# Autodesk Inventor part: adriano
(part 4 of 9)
sketch "スケッチ127"
  geometry: L1 (0.25, 9.936)-(0.25, 8.736) reference; L2 (0.25, 8.736)-(-0.75, 8.736) reference; L3 (-0.75, 8.736)-(-0.75, 9.936) reference; L4 (-0.75, 9.936)-(0.25, 9.936) reference; L5 (-12.75, 9.936)-(-12.75, 8.736) reference; L6 (-12.75, 8.736)-(-13.75, 8.736) reference; L7 (-13.75, 8.736)-(-13.75, 9.936) reference; L8 (-13.75, 9.936)-(-12.75, 9.936) reference; L9 (-12.75, 4.836)-(-12.75, 3.636) reference; L10 (-12.75, 3.636)-(-13.75, 3.636) reference; L11 (-13.75, 3.636)-(-13.75, 4.836) reference; L12 (-13.75, 4.836)-(-12.75, 4.836) reference; L13 (-12.75, 6.536)-(-12.75, 5.336) reference; L14 (-12.75, 5.336)-(-13.75, 5.336) reference; L15 (-13.75, 5.336)-(-13.75, 6.536) reference; L16 (-13.75, 6.536)-(-12.75, 6.536) reference; L17 (-12.75, 8.236)-(-12.75, 7.036) reference; L18 (-12.75, 7.036)-(-13.75, 7.036) reference; L19 (-13.75, 7.036)-(-13.75, 8.236) reference; L20 (-13.75, 8.236)-(-12.75, 8.236) reference; L21 (-1.25, 4.836)-(-1.25, 3.636) reference; L22 (-1.25, 3.636)-(-2.25, 3.636) reference; L23 (-2.25, 3.636)-(-2.25, 4.836) reference; L24 (-2.25, 4.836)-(-1.25, 4.836) reference; L25 (-1.25, 6.536)-(-1.25, 5.336) reference; L26 (-1.25, 5.336)-(-2.25, 5.336) reference; L27 (-2.25, 5.336)-(-2.25, 6.536) reference; L28 (-2.25, 6.536)-(-1.25, 6.536) reference; L29 (-1.25, 8.236)-(-1.25, 7.036) reference; L30 (-1.25, 7.036)-(-2.25, 7.036) reference; L31 (-2.25, 7.036)-(-2.25, 8.236) reference; L32 (-2.25, 8.236)-(-1.25, 8.236) reference; L33 (-13.75, 10.436)-(-13.75, 11.436) reference; L34 (-12.75, 10.436)-(-13.75, 10.436) reference; L35 (-0.75, 10.436)-(-0.75, 11.436) reference; L36 (0.25, 10.436)-(-0.75, 10.436) reference; L37 (-1.25, 10.436)-(-2.25, 10.436) reference; L38 (-1.25, 11.436)-(-1.25, 10.436) reference; L39 (-14.25, 10.436)-(-15.25, 10.436) reference; L40 (-14.25, 11.436)-(-14.25, 10.436) reference; L41 (0.25, 8.236)-(0.25, 7.036) reference; L42 (0.25, 7.036)-(-0.75, 7.036) reference; L43 (-0.75, 7.036)-(-0.75, 8.236) reference; L44 (-0.75, 8.236)-(0.25, 8.236) reference; L45 (0.25, 6.536)-(0.25, 5.336) reference; L46 (0.25, 5.336)-(-0.75, 5.336) reference; L47 (-0.75, 5.336)-(-0.75, 6.536) reference; L48 (-0.75, 6.536)-(0.25, 6.536) reference; L49 (0.25, 4.836)-(0.25, 3.636) reference; L50 (0.25, 3.636)-(-0.75, 3.636) reference; L51 (-0.75, 3.636)-(-0.75, 4.836) reference; L52 (-0.75, 4.836)-(0.25, 4.836) reference; L53 (-14.25, 8.236)-(-14.25, 7.036) reference; L54 (-14.25, 7.036)-(-15.25, 7.036) reference; L55 (-15.25, 7.036)-(-15.25, 8.236) reference; L56 (-15.25, 8.236)-(-14.25, 8.236) reference; L57 (-14.25, 6.536)-(-14.25, 5.336) reference; L58 (-14.25, 5.336)-(-15.25, 5.336) reference; L59 (-15.25, 5.336)-(-15.25, 6.536) reference; L60 (-15.25, 6.536)-(-14.25, 6.536) reference; L61 (-14.25, 4.836)-(-14.25, 3.636) reference; L62 (-14.25, 3.636)-(-15.25, 3.636) reference; L63 (-15.25, 3.636)-(-15.25, 4.836) reference; L64 (-15.25, 4.836)-(-14.25, 4.836) reference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; A1 r 1 centre (-13.75, 10.436) between (-12.75, 10.436) and (-13.75, 11.436) reference; A2 r 1 centre (-0.75, 10.436) between (0.25, 10.436) and (-0.75, 11.436) reference; A3 r 1 centre (-1.25, 10.436) between (-1.25, 11.436) and (-2.25, 10.436) reference; A4 r 1 centre (-14.25, 10.436) between (-14.25, 11.436) and (-15.25, 10.436) reference; A5 r 2 centre (-1, 10.436) between (1, 10.436) and (-3, 10.436); A6 r 2 centre (-14, 10.436) between (-12, 10.436) and (-16, 10.436); 2 further points
  constraints: 12 end point, 4 point on circle, 3 parallel, 3 perpendicular, 3 tangent, 2 centre point, 2 point on line
  dimensions: "d1680" = 3 distance between parallel lines of L73 L78; "d1681" = 4 distance of L77.end L78.end; "d1682" = 2 distance between parallel lines of L74 L79; "d1683" = 3 distance between parallel lines of L75 L81; "d1684" = 4 distance of L80.end L81.end; "d1685" = 2 distance between parallel lines of L83 L80
extrude "押し出し118" cut sketch "スケッチ127" distance "d1686" = 0.5; taper "d1687" = 0 deg
sketch "スケッチ129"
  geometry: L1 (86.588, 32.686)-(82.588, 32.686) reference; L2 (86.588, 32.686)-(86.588, 40.686) reference; L3 (86.588, 40.686)-(55.588, 40.686) reference; L4 (55.588, 40.686)-(55.588, 32.686) reference; L5 (59.588, 39.186)-(82.588, 39.186) reference; L6 (59.588, 39.186)-(59.588, 40.186) reference; L7 (59.588, 40.186)-(82.588, 40.186) reference; L8 (82.588, 40.186)-(82.588, 39.186) reference; L9 (56.588, 40.686)-(85.588, 40.686); L10 (85.588, 40.686)-(85.588, 32.686); L11 (85.588, 32.686)-(56.588, 32.686); L12 (56.588, 32.686)-(56.588, 40.686); 1 further point
  constraints: 8 end point, 2 parallel, 2 point on line, 1 horizontal, 1 perpendicular
  dimensions: "d1690" = 1 distance between parallel lines of L12 L4; "d1691" = 1 distance between parallel lines of L2 L10
extrude "押し出し119" join sketch "スケッチ129" distance "d1692" = 1; taper "d1693" = 0 deg
sketch "スケッチ130"
  geometry: L1 (29.588, -11.314)-(29.588, 10.686) reference; L2 (60.588, -11.314)-(29.588, -11.314) reference; L3 (81.588, -24.314)-(60.588, -24.314) reference; L4 (81.588, 23.686)-(81.588, -24.314) reference; L5 (60.588, 23.686)-(71.088, 23.686) reference; L6 (60.588, 10.686)-(60.588, 23.686) reference; L7 (29.588, 10.686)-(60.588, 10.686) reference; L8 (31.588, 8.686)-(31.588, -9.314); L9 (31.588, -9.314)-(62.588, -9.314); L10 (62.588, -9.314)-(62.588, -22.314); L11 (62.588, -22.314)-(79.588, -22.314); L12 (79.588, -22.314)-(79.588, 21.686); L13 (79.588, 21.686)-(62.588, 21.686); L14 (62.588, 21.686)-(62.588, 8.686); L15 (62.588, 8.686)-(31.588, 8.686); 1 further point
  constraints: 16 end point, 4 parallel, 4 perpendicular
  dimensions: "d1694" = 2 distance between parallel lines of L15 L7; "d1695" = 2 distance between parallel lines of L1 L8; "d1696" = 2 distance between parallel lines of L2 L9; "d1697" = 2 distance between parallel lines of L4 L12; "d1698" = 2 distance between parallel lines of L14 L6; "d1699" = 2 distance between parallel lines of L13 L5; "d1700" = 0 distance between parallel lines of L10 L14; "d1702" = 2 distance between parallel lines of L3 L11
extrude "押し出し120" cut sketch "スケッチ130" distance "d1703" = 12; taper "d1704" = 0 deg
sketch "スケッチ131"
  geometry: L1 (-30.683, 26.8)-(-30.683, 29.2) reference; L2 (-30.683, 29.2)-(-29.883, 29.2) reference; L3 (-29.883, 26.8)-(-30.683, 26.8) reference; L4 (-31.483, 29.2)-(-32.283, 29.2); L5 (-32.283, 29.2)-(-32.283, 26.8); L6 (-32.283, 26.8)-(-31.483, 26.8); L7 (-31.483, 26.8)-(-31.483, 29.2); L8 (-33.083, 29.2)-(-33.883, 29.2); L9 (-33.883, 29.2)-(-33.883, 26.8); L10 (-33.883, 26.8)-(-33.083, 26.8); L11 (-33.083, 26.8)-(-33.083, 29.2); L12 (-61.5, 29.2)-(-60.7, 29.2); L13 (-60.7, 29.2)-(-60.7, 26.749); L14 (-60.7, 26.749)-(-61.5, 26.749); L15 (-61.5, 26.749)-(-61.5, 29.2); L16 (-59.9, 29.2)-(-59.1, 29.2); L17 (-59.1, 29.2)-(-59.1, 26.749); L18 (-59.1, 26.749)-(-59.9, 26.749); L19 (-59.9, 26.749)-(-59.9, 29.2); L20 (-62.3, 29.2)-(-62.3, 26.749) reference; L21 (-62.3, 26.749)-(-63.1, 26.749) reference; 1 further point
  constraints: 32 end point, 8 parallel, 4 horizontal, 4 perpendicular
  dimensions: "d1705" = 0.8 distance of L4.start L4.end; "d1707" = 0.8 distance between parallel lines of L1 L7; "d1708" = 0.8 distance between parallel lines of L5 L11; "d1709" = 0 distance between parallel lines of L3 L6; "d1710" = 0 distance between parallel lines of L6 L10; "d1711" = 0 distance between parallel lines of L4 L8; "d1712" = 0 distance between parallel lines of L2 L4; "d1713" = 0.8 distance of L8.start L8.end; "d1714" = 0.8 distance of L12.start L12.end; "d1715" = 0.8 distance of L16.start L16.end; "d1716" = 0.8 distance between parallel lines of L19 L13; "d1717" = 0.8 distance between parallel lines of L15 L20; "d1718" = 0 distance between parallel lines of L14 L21; "d1719" = 0 distance between parallel lines of L18 L14
extrude "押し出し121" cut sketch "スケッチ131" distance "d1720" = 2; taper "d1721" = 0 deg
sketch "スケッチ132"
  geometry: L1 (-0.5, -19.064)-(30.5, -19.064) reference; L2 (4, -8.3)-(5, -8.3); L3 (5, -8.3)-(5, -9.5); L4 (5, -9.5)-(4, -9.5); L5 (4, -9.5)-(4, -8.3); L6 (5.5, -8.3)-(6.5, -8.3); L7 (6.5, -8.3)-(6.5, -9.5); L8 (6.5, -9.5)-(5.5, -9.5); L9 (5.5, -9.5)-(5.5, -8.3); L10 (10.5, -8.3)-(11.5, -8.3); L11 (11.5, -8.3)-(11.5, -9.5); L12 (11.5, -9.5)-(10.5, -9.5); L13 (10.5, -9.5)-(10.5, -8.3); L14 (12, -8.3)-(13, -8.3); L15 (13, -8.3)-(13, -9.5); L16 (13, -9.5)-(12, -9.5); L17 (12, -9.5)-(12, -8.3); L18 (17, -8.3)-(18, -8.3); L19 (18, -8.3)-(18, -9.5); L20 (18, -9.5)-(17, -9.5); L21 (17, -9.5)-(17, -8.3); L22 (18.5, -8.3)-(19.5, -8.3); L23 (19.5, -8.3)-(19.5, -9.5); L24 (19.5, -9.5)-(18.5, -9.5); L25 (18.5, -9.5)-(18.5, -8.3); L26 (23.5, -8.3)-(24.5, -8.3); L27 (24.5, -8.3)-(24.5, -9.5); L28 (24.5, -9.5)-(23.5, -9.5); L29 (23.5, -9.5)-(23.5, -8.3); L30 (25, -8.3)-(26, -8.3); L31 (26, -8.3)-(26, -9.5); L32 (26, -9.5)-(25, -9.5); L33 (25, -9.5)-(25, -8.3); L34 (10.5, -7.8)-(10.5, -6.6); L35 (10.5, -6.6)-(11.5, -6.6); L36 (11.5, -7.8)-(10.5, -7.8); L37 (11.5, -6.6)-(11.5, -7.8); L38 (12, -7.8)-(12, -6.6); L39 (13, -6.6)-(13, -7.8); L40 (13, -7.8)-(12, -7.8); L41 (12, -6.6)-(13, -6.6); L42 (17, -7.8)-(17, -6.6); L43 (17, -6.6)-(18, -6.6); L44 (18, -7.8)-(17, -7.8); L45 (18, -6.6)-(18, -7.8); L46 (18.5, -7.8)-(18.5, -6.6); L47 (19.5, -6.6)-(19.5, -7.8); L48 (18.5, -6.6)-(19.5, -6.6); L49 (19.5, -7.8)-(18.5, -7.8); L50 (23.5, -7.8)-(23.5, -6.6); L51 (23.5, -6.6)-(24.5, -6.6); L52 (24.5, -6.6)-(24.5, -7.8); L53 (25, -7.8)-(25, -6.6); L54 (25, -6.6)-(26, -6.6); L55 (26, -6.6)-(26, -7.8); L56 (26, -7.8)-(25, -7.8); L57 (24.5, -7.8)-(23.5, -7.8); L58 (6.5, -6.6)-(6.5, -7.8); L59 (5.5, -6.6)-(6.5, -6.6); L60 (6.5, -7.8)-(5.5, -7.8); L61 (5.5, -7.8)-(5.5, -6.6); L62 (5, -6.6)-(5, -7.8); L63 (4, -6.6)-(5, -6.6); L64 (5, -7.8)-(4, -7.8)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; A1 r 1 centre (5, -23.564) between (5, -22.564) and (4, -23.564); A2 r 1 centre (5.5, -23.564) between (6.5, -23.564) and (5.5, -22.564); A3 r 1 centre (11.5, -23.564) between (11.5, -22.564) and (10.5, -23.564); A4 r 1 centre (12, -23.564) between (13, -23.564) and (12, -22.564); A5 r 1 centre (18, -23.564) between (18, -22.564) and (17, -23.564); A6 r 1 centre (18.5, -23.564) between (19.5, -23.564) and (18.5, -22.564); A7 r 1 centre (24.5, -23.564) between (24.5, -22.564) and (23.5, -23.564); A8 r 1 centre (25, -23.564) between (26, -23.564) and (25, -22.564); 2 further points
  constraints: 544 end point, 131 parallel, 75 perpendicular, 64 horizontal, 16 point on circle, 8 centre point, 2 collinear
  dimensions: "d1722" = 1 distance of L63.start L62.start; "d1724" = 0.5 distance between parallel lines of L61 L62; "d1725" = 1 distance of L59.start L58.start; "d1726" = 4 distance between parallel lines of L34 L58; "d1727" = 1 distance of L34.end L35.end; "d1728" = 0.5 distance between parallel lines of L38 L37; "d1729" = 1 distance of L38.end L39.start; "d1730" = 1 distance of L42.end L43.end; "d1731" = 0.5 distance between parallel lines of L46 L45; "d1732" = 1 distance of L46.end L47.start; "d1733" = 1 distance of L50.end L51.end; "d1734" = 0.5 distance between parallel lines of L53 L52; "d1735" = 1 distance of L53.end L54.end; "d1736" = 4 distance between parallel lines of L50 L47; "d1737" = 4 distance between parallel lines of L42 L39; "d1738" = 0 distance between parallel lines of L55 L31; "d1739" = 0 distance between parallel lines of L31 L107; "d1740" = 0 distance between parallel lines of L107 L98; "d1741" = 0 distance between parallel lines of L52 L27; "d1742" = 0 distance between parallel lines of L27 L111; "d1743" = 0 distance between parallel lines of L111 L102; "d1744" = 0 distance between parallel lines of L47 L23; "d1745" = 0 distance between parallel lines of L90 L23; "d1746" = 0 distance between parallel lines of L87 L90; "d1747" = 0 distance between parallel lines of L45 L19; "d1748" = 0 distance between parallel lines of L19 L94; "d1749" = 0 distance between parallel lines of L94 L83; "d1750" = 0 distance between parallel lines of L39 L15; "d1751" = 0 distance between parallel lines of L15 L80; "d1752" = 0 distance between parallel lines of L80 L71; "d1753" = 0 distance between parallel lines of L11 L37; "d1754" = 0 distance between parallel lines of L76 L11; "d1755" = 0 distance between parallel lines of L76 L67; "d1756" = 0 distance between parallel lines of L13 L34; "d1757" = 0 distance between parallel lines of L73 L13; "d1758" = 0 distance between parallel lines of L69 L73; "d1759" = 0 distance between parallel lines of L21 L42; "d1760" = 0 distance between parallel lines of L96 L21; "d1761" = 0 distance between parallel lines of L85 L96; "d1762" = 0 distance between parallel lines of L25 L46; "d1763" = 0 distance between parallel lines of L93 L25; "d1764" = 0 distance between parallel lines of L89 L93; "d1765" = 0 distance between parallel lines of L29 L50; "d1766" = 0 distance between parallel lines of L112 L29; "d1767" = 0 distance between parallel lines of L105 L112; "d1768" = 0 distance between parallel lines of L33 L53; "d1769" = 0 distance between parallel lines of L109 L33; "d1770" = 0 distance between parallel lines of L101 L109; "d1771" = 0 distance between parallel lines of L17 L38; "d1772" = 0 distance between parallel lines of L77 L17; "d1773" = 0 distance between parallel lines of L78 L77; "d1774" = 0 distance between parallel lines of L9 L61; "d1775" = 0 distance between parallel lines of L125 L9; "d1776" = 0 distance between parallel lines of L119 L125; "d1777" = 0 distance between parallel lines of L7 L58; "d1778" = 0 distance between parallel lines of L123 L7; "d1779" = 0 distance between parallel lines of L118 L123; "d1780" = 1.2 distance of L64.end L63.start; "d1781" = 0.5 distance between parallel lines of L2 L64; "d1782" = 0.5 distance between parallel lines of L4 L127; "d1783" = 0.5 distance between parallel lines of L121 L129; "d1784" = 1.2 distance of L4.end L2.start; "d1785" = 1.2 distance of L128.start L127.start; "d1786" = 1.2 distance of L114.end L117.end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
extrude "押し出し122" cut sketch "スケッチ132" distance "d1985" = 30; taper "d1986" = 0 deg
sketch "スケッチ133"
  geometry: L1 (5.5, -10)-(6.5, -10) reference; L2 (6.5, -10)-(6.5, -11.2) reference; L3 (6.5, -11.2)-(5.5, -11.2) reference; L4 (5.5, -11.2)-(5.5, -10) reference; L5 (23.5, -10)-(24.5, -10) reference; L6 (24.5, -10)-(24.5, -11.2) reference; L7 (24.5, -11.2)-(23.5, -11.2) reference; L8 (23.5, -11.2)-(23.5, -10) reference; L9 (23.5, -11.7)-(24.5, -11.7) reference; L10 (24.5, -11.7)-(24.5, -12.9) reference; L11 (24.5, -12.9)-(23.5, -12.9) reference; L12 (23.5, -12.9)-(23.5, -11.7) reference; L13 (18.5, -11.2)-(18.5, -10) reference; L14 (18.5, -10)-(19.5, -10) reference; L15 (19.5, -10)-(19.5, -11.2) reference; L16 (19.5, -11.2)-(18.5, -11.2) reference; L17 (17, -12.9)-(17, -11.7) reference; L18 (17, -11.7)-(18, -11.7) reference; L19 (18, -11.7)-(18, -12.9) reference; L20 (18, -12.9)-(17, -12.9) reference; L21 (10.5, -11.2)-(10.5, -10) reference; L22 (10.5, -10)-(11.5, -10) reference; L23 (11.5, -10)-(11.5, -11.2) reference; L24 (11.5, -11.2)-(10.5, -11.2) reference; L25 (10.5, -12.9)-(10.5, -11.7) reference; L26 (10.5, -11.7)-(11.5, -11.7) reference; L27 (11.5, -11.7)-(11.5, -12.9) reference; L28 (11.5, -12.9)-(10.5, -12.9) reference; L29 (6.5, -11.7)-(6.5, -12.9) reference; L30 (6.5, -12.9)-(5.5, -12.9) reference; L31 (5.5, -12.9)-(5.5, -11.7) reference; L32 (5.5, -11.7)-(6.5, -11.7) reference; L33 (5.5, -6.6)-(6.5, -6.6) reference; L34 (6.5, -6.6)-(6.5, -7.8) reference; L35 (6.5, -7.8)-(5.5, -7.8) reference; L36 (5.5, -7.8)-(5.5, -6.6) reference; L37 (23.5, -7.8)-(23.5, -6.6) reference; L38 (23.5, -6.6)-(24.5, -6.6) reference; L39 (24.5, -6.6)-(24.5, -7.8) reference; L40 (24.5, -7.8)-(23.5, -7.8) reference; L41 (17, -7.8)-(17, -6.6) reference; L42 (17, -6.6)-(18, -6.6) reference; L43 (18, -6.6)-(18, -7.8) reference; L44 (18, -7.8)-(17, -7.8) reference; L45 (10.5, -7.8)-(10.5, -6.6) reference; L46 (10.5, -6.6)-(11.5, -6.6) reference; L47 (11.5, -6.6)-(11.5, -7.8) reference; L48 (11.5, -7.8)-(10.5, -7.8) reference; L49 (23.5, -9.5)-(23.5, -8.3) reference; L50 (23.5, -8.3)-(24.5, -8.3) reference; L51 (24.5, -8.3)-(24.5, -9.5) reference; L52 (24.5, -9.5)-(23.5, -9.5) reference; L53 (17, -9.5)-(17, -8.3) reference; L54 (17, -8.3)-(18, -8.3) reference; L55 (18, -8.3)-(18, -9.5) reference; L56 (18, -9.5)-(17, -9.5) reference; L57 (10.5, -9.5)-(10.5, -8.3) reference; L58 (10.5, -8.3)-(11.5, -8.3) reference; L59 (11.5, -8.3)-(11.5, -9.5) reference; L60 (11.5, -9.5)-(10.5, -9.5) reference; L61 (4, -9.5)-(4, -8.3) reference; L62 (4, -8.3)-(5, -8.3) reference; L63 (5, -8.3)-(5, -9.5) reference; L64 (5, -9.5)-(4, -9.5) reference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; A1 r 2 centre (5.25, -23.564) between (7.25, -23.564) and (3.25, -23.564); A2 r 2 centre (11.75, -23.564) between (13.75, -23.564) and (9.75, -23.564); A3 r 2 centre (18.25, -23.564) between (20.25, -23.564) and (16.25, -23.564); A4 r 2 centre (24.75, -23.564) between (26.75, -23.564) and (22.75, -23.564); 2 further points
  constraints: 56 end point, 16 parallel, 8 perpendicular, 8 point on circle, 8 tangent, 4 centre point, 4 horizontal
  dimensions: "d1987" = 4 distance of L132.end L133.end; "d1989" = 4 distance of L136.end L137.end; "d1990" = 4 distance of L140.end L141.end; "d1991" = 4 distance of L144.end L145.end; "d1992" = 3.75 distance between parallel lines of L129 L144; "d1993" = 2.5 distance between parallel lines of L146 L140; "d1994" = 2.5 distance between parallel lines of L136 L142; "d1995" = 2.5 distance between parallel lines of L132 L138; "d1996" = 0 distance between parallel lines of L147 L134; "d1997" = 0 distance between parallel lines of L149 L132; "d1998" = 0 distance between parallel lines of L150 L138; "d1999" = 0 distance between parallel lines of L152 L136; "d2000" = 0 distance between parallel lines of L153 L142; "d2001" = 0 distance between parallel lines of L155 L140; "d2002" = 0 distance between parallel lines of L158 L144; "d2003" = 0 distance between parallel lines of L146 L156; "d2004" = 4.35 distance between parallel lines of L143 L130; "d2005" = 0 distance between parallel lines of L143 L139; "d2006" = 0 distance from line of L139 L135.end; "d2007" = 0 distance between parallel lines of L131 L135; "d2008" = 7.5 distance of L143.end L144.end; "d2009" = 0 distance from line of L159 A4.centre; "d2010" = 0 vertical distance of A4.centre A3.centre; "d2011" = 0 vertical distance of A3.centre A2.centre; "d2012" = 0 vertical distance of A1.centre A2.centre; "d2013" = 3 distance between parallel lines of L160 L157; "d2014" = 0 distance between parallel lines of L157 L154; "d2015" = 0 distance between parallel lines of L151 L154; "d2016" = 0 distance between parallel lines of L151 L148
extrude "押し出し123" cut sketch "スケッチ133" distance "d2017" = 0.5; taper "d2018" = 0 deg
sketch "スケッチ134"
  geometry: L1 (24.5, -10)-(25.5, -10) reference; L2 (25.5, -10)-(25.5, -11.2) reference; L3 (25.5, -11.2)-(24.5, -11.2) reference; L4 (24.5, -11.2)-(24.5, -10) reference; L5 (6.5, -10)-(7.5, -10) reference; L6 (7.5, -10)-(7.5, -11.2) reference; L7 (7.5, -11.2)-(6.5, -11.2) reference; L8 (6.5, -11.2)-(6.5, -10) reference; L9 (6.5, -11.7)-(7.5, -11.7) reference; L10 (7.5, -11.7)-(7.5, -12.9) reference; L11 (7.5, -12.9)-(6.5, -12.9) reference; L12 (6.5, -12.9)-(6.5, -11.7) reference; L13 (12.5, -10)-(12.5, -11.2) reference; L14 (12.5, -11.2)-(11.5, -11.2) reference; L15 (11.5, -11.2)-(11.5, -10) reference; L16 (11.5, -10)-(12.5, -10) reference; L17 (14, -11.7)-(14, -12.9) reference; L18 (14, -12.9)-(13, -12.9) reference; L19 (13, -12.9)-(13, -11.7) reference; L20 (13, -11.7)-(14, -11.7) reference; L21 (20.5, -10)-(20.5, -11.2) reference; L22 (20.5, -11.2)-(19.5, -11.2) reference; L23 (19.5, -11.2)-(19.5, -10) reference; L24 (19.5, -10)-(20.5, -10) reference; L25 (20.5, -11.7)-(20.5, -12.9) reference; L26 (20.5, -12.9)-(19.5, -12.9) reference; L27 (19.5, -12.9)-(19.5, -11.7) reference; L28 (19.5, -11.7)-(20.5, -11.7) reference; L29 (24.5, -12.9)-(24.5, -11.7) reference; L30 (24.5, -11.7)-(25.5, -11.7) reference; L31 (25.5, -11.7)-(25.5, -12.9) reference; L32 (25.5, -12.9)-(24.5, -12.9) reference; L33 (24.5, -6.6)-(25.5, -6.6) reference; L34 (25.5, -6.6)-(25.5, -7.8) reference; L35 (25.5, -7.8)-(24.5, -7.8) reference; L36 (24.5, -7.8)-(24.5, -6.6) reference; L37 (7.5, -6.6)-(7.5, -7.8) reference; L38 (7.5, -7.8)-(6.5, -7.8) reference; L39 (6.5, -7.8)-(6.5, -6.6) reference; L40 (6.5, -6.6)-(7.5, -6.6) reference; L41 (14, -6.6)-(14, -7.8) reference; L42 (14, -7.8)-(13, -7.8) reference; L43 (13, -7.8)-(13, -6.6) reference; L44 (13, -6.6)-(14, -6.6) reference; L45 (20.5, -6.6)-(20.5, -7.8) reference; L46 (20.5, -7.8)-(19.5, -7.8) reference; L47 (19.5, -7.8)-(19.5, -6.6) reference; L48 (19.5, -6.6)-(20.5, -6.6) reference; L49 (7.5, -8.3)-(7.5, -9.5) reference; L50 (7.5, -9.5)-(6.5, -9.5) reference; L51 (6.5, -9.5)-(6.5, -8.3) reference; L52 (6.5, -8.3)-(7.5, -8.3) reference; L53 (14, -8.3)-(14, -9.5) reference; L54 (14, -9.5)-(13, -9.5) reference; L55 (13, -9.5)-(13, -8.3) reference; L56 (13, -8.3)-(14, -8.3) reference; L57 (20.5, -8.3)-(20.5, -9.5) reference; L58 (20.5, -9.5)-(19.5, -9.5) reference; L59 (19.5, -9.5)-(19.5, -8.3) reference; L60 (19.5, -8.3)-(20.5, -8.3) reference; L61 (27, -8.3)-(27, -9.5) reference; L62 (27, -9.5)-(26, -9.5) reference; L63 (26, -9.5)-(26, -8.3) reference; L64 (26, -8.3)-(27, -8.3) reference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; A1 r 2 centre (6.25, -23.564) between (8.25, -23.564) and (4.25, -23.564); A2 r 2 centre (12.75, -23.564) between (14.75, -23.564) and (10.75, -23.564); A3 r 2 centre (19.25, -23.564) between (21.25, -23.564) and (17.25, -23.564); A4 r 2 centre (25.75, -23.564) between (27.75, -23.564) and (23.75, -23.564); 2 further points
  constraints: 56 end point, 16 parallel, 8 perpendicular, 8 point on circle, 8 tangent, 4 centre point, 4 horizontal
  dimensions: "d2019" = 4 distance of L131.start L131.end; "d2021" = 4 distance of L135.start L135.end; "d2022" = 4 distance of L139.start L139.end; "d2023" = 4 distance of L143.start L143.end; "d2024" = 3.75 distance between parallel lines of L130 L134; "d2025" = 2.5 distance between parallel lines of L138 L132; "d2026" = 2.5 distance between parallel lines of L142 L136; "d2027" = 2.5 distance between parallel lines of L146 L140; "d2028" = 7.5 distance of L133.end L131.start; "d2029" = 4.3 distance between parallel lines of L129 L139; "d2030" = 0 distance between parallel lines of L135 L139; "d2031" = 0 distance between parallel lines of L135 L131; "d2032" = 0 distance between parallel lines of L137 L159; "d2033" = 0 distance between parallel lines of L141 L137; "d2034" = 0 distance between parallel lines of L145 L141; "d2035" = 0 distance between parallel lines of L147 L134; "d2036" = 0 distance between parallel lines of L149 L132; "d2037" = 0 distance between parallel lines of L138 L150; "d2038" = 0 distance between parallel lines of L152 L136; "d2039" = 0 distance between parallel lines of L153 L142; "d2040" = 0 distance between parallel lines of L140 L155; "d2041" = 0 distance between parallel lines of L156 L146; "d2042" = 0 distance between parallel lines of L158 L144; "d2044" = 0 distance from line of L161 A1.centre; "d2045" = 0 vertical distance of A2.centre A1.centre; "d2046" = 0 vertical distance of A2.centre A3.centre; "d2047" = 0 vertical distance of A4.centre A3.centre; "d2048" = 3 distance between parallel lines of L162 L157; "d2049" = 0 distance between parallel lines of L157 L154; "d2050" = 0 distance between parallel lines of L154 L151; "d2051" = 0 distance between parallel lines of L151 L148
extrude "押し出し124" cut sketch "スケッチ134" distance "d2052" = 0.5; taper "d2053" = 0 deg
sketch "スケッチ135"
  geometry: L1 (-25.5, 32.4)-(-0.5, 32.4) reference; L2 (-25.5, 16.536)-(-25.5, 32.4) reference; L3 (-20.5, 27.4)-(-19.5, 27.4); L4 (-19.5, 27.4)-(-19.5, 26.2); L5 (-19.5, 26.2)-(-20.5, 26.2); L6 (-20.5, 26.2)-(-20.5, 27.4); L7 (-19, 27.4)-(-18, 27.4); L8 (-18, 27.4)-(-18, 26.2); L9 (-18, 26.2)-(-19, 26.2); L10 (-19, 26.2)-(-19, 27.4); L11 (-20.5, 25.7)-(-19.5, 25.7); L12 (-19.5, 25.7)-(-19.5, 24.5); L13 (-19.5, 24.5)-(-20.5, 24.5); L14 (-20.5, 24.5)-(-20.5, 25.7); L15 (-19, 25.7)-(-18, 25.7); L16 (-18, 25.7)-(-18, 24.5); L17 (-18, 24.5)-(-19, 24.5); L18 (-19, 24.5)-(-19, 25.7); L19 (-18, 21.1)-(-19, 21.1); L20 (-19.5, 21.1)-(-20.5, 21.1); L21 (-18, 22.3)-(-18, 21.1); L22 (-19, 21.1)-(-19, 22.3); L23 (-19.5, 22.3)-(-19.5, 21.1); L24 (-20.5, 21.1)-(-20.5, 22.3); L25 (-19, 22.3)-(-18, 22.3); L26 (-20.5, 22.3)-(-19.5, 22.3); L27 (-18, 22.8)-(-19, 22.8); L28 (-19.5, 22.8)-(-20.5, 22.8); L29 (-20.5, 24)-(-19.5, 24); L30 (-20.5, 22.8)-(-20.5, 24); L31 (-19.5, 24)-(-19.5, 22.8); L32 (-19, 24)-(-18, 24); L33 (-19, 22.8)-(-19, 24); L34 (-18, 24)-(-18, 22.8); L35 (-11.5, 21.1)-(-12.5, 21.1); L36 (-14, 25.7)-(-13, 25.7); L37 (-13, 24.5)-(-14, 24.5); L38 (-14, 24.5)-(-14, 25.7); L39 (-11.5, 25.7)-(-11.5, 24.5); L40 (-11.5, 24.5)-(-12.5, 24.5); L41 (-12.5, 24.5)-(-12.5, 25.7); L42 (-12.5, 25.7)-(-11.5, 25.7); L43 (-13, 25.7)-(-13, 24.5); L44 (-12.5, 24)-(-11.5, 24); L45 (-13, 26.2)-(-14, 26.2); L46 (-11.5, 26.2)-(-12.5, 26.2); L47 (-14, 26.2)-(-14, 27.4); L48 (-14, 27.4)-(-13, 27.4); L49 (-13, 27.4)-(-13, 26.2); L50 (-12.5, 27.4)-(-11.5, 27.4); L51 (-12.5, 26.2)-(-12.5, 27.4); L52 (-11.5, 27.4)-(-11.5, 26.2); L53 (-13, 21.1)-(-14, 21.1); L54 (-11.5, 22.3)-(-11.5, 21.1); L55 (-12.5, 22.3)-(-11.5, 22.3); L56 (-12.5, 21.1)-(-12.5, 22.3); L57 (-13, 22.3)-(-13, 21.1); L58 (-14, 22.3)-(-13, 22.3); L59 (-14, 21.1)-(-14, 22.3); L60 (-11.5, 22.8)-(-12.5, 22.8); L61 (-13, 22.8)-(-14, 22.8); L62 (-11.5, 24)-(-11.5, 22.8); L63 (-12.5, 22.8)-(-12.5, 24); L64 (-13, 24)-(-13, 22.8)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; A1 r 1 centre (-19.5, 10.436) between (-19.5, 11.436) and (-20.5, 10.436); A2 r 1 centre (-19, 10.436) between (-18, 10.436) and (-19, 11.436); A3 r 1 centre (-13, 10.436) between (-13, 11.436) and (-14, 10.436); A4 r 1 centre (-12.5, 10.436) between (-11.5, 10.436) and (-12.5, 11.436); A5 r 1 centre (-6.5, 10.436) between (-6.5, 11.436) and (-7.5, 10.436); A6 r 1 centre (-6, 10.436) between (-5, 10.436) and (-6, 11.436); 2 further points
  constraints: 408 end point, 100 parallel, 54 perpendicular, 48 horizontal, 12 point on circle, 6 centre point, 2 collinear
  dimensions: "d2057" = 1 distance of L3.start L3.end; "d2059" = 1.2 distance of L5.end L3.start; "d2060" = 1 distance of L7.start L7.end; "d2061" = 1.2 distance of L9.end L7.start; "d2062" = 0.5 distance between parallel lines of L10 L4; "d2063" = 0 distance between parallel lines of L7 L3; "d2064" = 1 distance of L11.start L11.end; "d2065" = 1.2 distance of L13.end L11.start; "d2066" = 1 distance of L15.start L15.end; "d2067" = 1.2 distance of L17.end L15.start; "d2068" = 0.5 distance between parallel lines of L18 L12; "d2069" = 0 distance between parallel lines of L15 L11; "d2070" = 0.5 distance between parallel lines of L11 L5; "d2071" = 0 distance between parallel lines of L14 L6; "d2072" = 1 distance of L29.start L29.end; "d2073" = 1.2 distance of L28.end L29.start; "d2074" = 1 distance of L32.start L32.end; "d2075" = 1.2 distance of L27.end L32.start; "d2076" = 0.5 distance between parallel lines of L33 L31; "d2077" = 0 distance between parallel lines of L32 L29; "d2078" = 1 distance of L24.end L23.start; "d2079" = 1.2 distance of L20.end L24.end; "d2080" = 1 distance of L22.end L21.start; "d2081" = 1.2 distance of L19.end L22.end; "d2082" = 0.5 distance between parallel lines of L22 L23; "d2083" = 0 distance between parallel lines of L25 L26; "d2084" = 0.5 distance between parallel lines of L26 L28; "d2085" = 0 distance between parallel lines of L24 L30; "d2086" = 0.5 distance between parallel lines of L29 L13; "d2087" = 0 distance between parallel lines of L30 L14; "d2088" = 1 distance of L47.end L48.end; "d2089" = 1.2 distance of L45.end L47.end; "d2090" = 1 distance of L50.start L50.end; "d2091" = 1.2 distance of L46.end L50.start; "d2092" = 0.5 distance between parallel lines of L51 L49; "d2093" = 0 distance between parallel lines of L50 L48; "d2094" = 1 distance of L36.start L36.end; "d2095" = 1.2 distance of L37.end L36.start; "d2096" = 1 distance of L41.end L39.start; "d2097" = 1.2 distance of L40.end L41.end; "d2098" = 0.5 distance between parallel lines of L41 L43; "d2099" = 0 distance between parallel lines of L42 L36; "d2100" = 0.5 distance between parallel lines of L36 L45; "d2101" = 0 distance between parallel lines of L38 L47; "d2102" = 1 distance of L65.start L64.start; "d2103" = 1.2 distance of L61.end L65.start; "d2104" = 1 distance of L44.start L44.end; "d2105" = 1.2 distance of L60.end L44.start; "d2106" = 0.5 distance between parallel lines of L63 L64; "d2107" = 0 distance between parallel lines of L44 L65; "d2108" = 1 distance of L58.start L57.start; "d2109" = 1.2 distance of L53.end L58.start; "d2110" = 1 distance of L55.start L54.start; "d2111" = 1.2 distance of L35.end L55.start; "d2112" = 0.5 distance between parallel lines of L56 L57; "d2113" = 0 distance between parallel lines of L55 L58; "d2114" = 0.5 distance between parallel lines of L58 L61; "d2115" = 0 distance between parallel lines of L59 L66; "d2116" = 0.5 distance between parallel lines of L65 L37; "d2117" = 0 distance between parallel lines of L66 L38; "d2118" = 1 distance of L96.end L95.start; "d2119" = 1.2 distance of L91.end L96.end; "d2120" = 1 distance of L94.start L93.start; "d2121" = 1.2 distance of L92.end L94.start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
extrude "押し出し125" cut sketch "スケッチ135" distance "d2256" = 2; taper "d2257" = 0 deg
sketch "スケッチ136"
  geometry: L1 (-7.5, 26.2)-(-7.5, 27.4) reference; L2 (-7.5, 27.4)-(-6.5, 27.4) reference; L3 (-6.5, 27.4)-(-6.5, 26.2) reference; L4 (-6.5, 26.2)-(-7.5, 26.2) reference; L5 (-7.5, 24.5)-(-7.5, 25.7) reference; L6 (-7.5, 25.7)-(-6.5, 25.7) reference; L7 (-6.5, 25.7)-(-6.5, 24.5) reference; L8 (-6.5, 24.5)-(-7.5, 24.5) reference; L9 (-6, 21.1)-(-6, 22.3) reference; L10 (-6, 22.3)-(-5, 22.3) reference; L11 (-5, 22.3)-(-5, 21.1) reference; L12 (-5, 21.1)-(-6, 21.1) reference; L13 (-7.5, 21.1)-(-7.5, 22.3) reference; L14 (-7.5, 22.3)-(-6.5, 22.3) reference; L15 (-6.5, 22.3)-(-6.5, 21.1) reference; L16 (-6.5, 21.1)-(-7.5, 21.1) reference; L17 (-12.5, 27.4)-(-11.5, 27.4) reference; L18 (-11.5, 27.4)-(-11.5, 26.2) reference; L19 (-11.5, 26.2)-(-12.5, 26.2) reference; L20 (-12.5, 26.2)-(-12.5, 27.4) reference; L21 (-12.5, 22.8)-(-12.5, 24) reference; L22 (-12.5, 24)-(-11.5, 24) reference; L23 (-11.5, 24)-(-11.5, 22.8) reference; L24 (-11.5, 22.8)-(-12.5, 22.8) reference; L25 (-12.5, 24.5)-(-12.5, 25.7) reference; L26 (-12.5, 25.7)-(-11.5, 25.7) reference; L27 (-11.5, 25.7)-(-11.5, 24.5) reference; L28 (-11.5, 24.5)-(-12.5, 24.5) reference; L29 (-12.5, 22.3)-(-11.5, 22.3) reference; L30 (-11.5, 22.3)-(-11.5, 21.1) reference; L31 (-11.5, 21.1)-(-12.5, 21.1) reference; L32 (-12.5, 21.1)-(-12.5, 22.3) reference; L33 (-18, 24)-(-18, 22.8) reference; L34 (-18, 22.8)-(-19, 22.8) reference; L35 (-19, 22.8)-(-19, 24) reference; L36 (-19, 24)-(-18, 24) reference; L37 (-18, 22.3)-(-18, 21.1) reference; L38 (-18, 21.1)-(-19, 21.1) reference; L39 (-19, 21.1)-(-19, 22.3) reference; L40 (-19, 22.3)-(-18, 22.3) reference; L41 (-20.5, 24.5)-(-20.5, 25.7) reference; L42 (-20.5, 25.7)-(-19.5, 25.7) reference; L43 (-19.5, 25.7)-(-19.5, 24.5) reference; L44 (-19.5, 24.5)-(-20.5, 24.5) reference; L45 (-20.5, 26.2)-(-20.5, 27.4) reference; L46 (-20.5, 27.4)-(-19.5, 27.4) reference; L47 (-19.5, 27.4)-(-19.5, 26.2) reference; L48 (-19.5, 26.2)-(-20.5, 26.2) reference; L49 (-19, 26.2)-(-19, 27.4) reference; L50 (-19, 27.4)-(-18, 27.4) reference; L51 (-18, 27.4)-(-18, 26.2) reference; L52 (-18, 26.2)-(-19, 26.2) reference; L53 (-19, 24.5)-(-19, 25.7) reference; L54 (-19, 25.7)-(-18, 25.7) reference; L55 (-18, 25.7)-(-18, 24.5) reference; L56 (-18, 24.5)-(-19, 24.5) reference; L57 (-20.5, 22.3)-(-19.5, 22.3) reference; L58 (-19.5, 22.3)-(-19.5, 21.1) reference; L59 (-19.5, 21.1)-(-20.5, 21.1) reference; L60 (-20.5, 21.1)-(-20.5, 22.3) reference; L61 (-20.5, 24)-(-19.5, 24) reference; L62 (-19.5, 24)-(-19.5, 22.8) reference; L63 (-19.5, 22.8)-(-20.5, 22.8) reference; L64 (-20.5, 22.8)-(-20.5, 24) reference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; A1 r 2 centre (-19.25, 10.5) between (-17.25, 10.5) and (-21.25, 10.5); A2 r 2 centre (-12.75, 10.5) between (-10.75, 10.5) and (-14.75, 10.5); A3 r 2 centre (-6.25, 10.5) between (-4.25, 10.5) and (-8.25, 10.5); 2 further points
  constraints: 42 end point, 12 parallel, 6 perpendicular, 6 point on circle, 6 tangent, 3 centre point, 3 horizontal
  dimensions: "d2258" = 4 distance of L99.start L99.end; "d2260" = 4 distance of L103.start L103.end; "d2261" = 4 distance of L107.start L107.end; "d2263" = 7.5 distance of L107.end L108.end; "d2264" = 4.5 distance between parallel lines of L98 L99; "d2265" = 0 distance between parallel lines of L103 L99; "d2266" = 0 distance between parallel lines of L107 L103; "d2267" = 2.5 distance between parallel lines of L106 L100; "d2268" = 2.5 distance between parallel lines of L109 L104; "d2269" = 0 distance between parallel lines of L113 L106; "d2271" = 0 distance between parallel lines of L105 L101; "d2274" = 0 distance between parallel lines of L118 L108; "d2275" = 3.75 distance between parallel lines of L97 L108; "d2276" = 0 distance between parallel lines of L115 L104; "d2277" = 0 distance between parallel lines of L116 L109; "d2278" = 0 distance between parallel lines of L112 L100; "d2279" = 3 distance between parallel lines of L120 L117; "d2280" = 0 distance between parallel lines of L114 L117; "d2281" = 0 distance between parallel lines of L114 L111; "d2282" = 7.5 distance of L117.end L118.end; "d2283" = 0 vertical distance of A3.centre A2.centre; "d2284" = 0 vertical distance of A1.centre A2.centre
extrude "押し出し126" cut sketch "スケッチ136" distance "d2285" = 0.5; taper "d2286" = 0 deg
sketch "スケッチ137"
  geometry: L1 (3.75, 20.536)-(3.75, 28.036) reference; L2 (3.75, 28.036)-(7.75, 28.036) reference; L3 (7.75, 28.036)-(7.75, 20.536) reference; L4 (3.75, 27.536)-(3.25, 27.536); L5 (3.25, 27.536)-(3.25, 28.536); L6 (3.25, 28.536)-(8.25, 28.536); L7 (8.25, 28.536)-(8.25, 27.536); L8 (8.25, 27.536)-(7.75, 27.536); L9 (7.75, 28.036)-(3.75, 28.036); L10 (3.75, 28.036)-(3.75, 27.536); L11 (7.75, 28.036)-(7.75, 27.536); L12 (14.75, 28.036)-(14.75, 27.536); L13 (10.75, 28.036)-(10.75, 27.536); L14 (10.25, 27.536)-(10.25, 28.536); L15 (10.75, 27.536)-(10.25, 27.536); L16 (14.75, 28.036)-(10.75, 28.036); L17 (15.152, 27.536)-(14.75, 27.536); L18 (15.212, 28.536)-(15.152, 27.536); L19 (10.25, 28.536)-(15.212, 28.536); L20 (43.69, 27.536)-(43.69, 28.536); L21 (44.19, 28.036)-(44.19, 27.536); L22 (44.19, 27.536)-(43.69, 27.536); L23 (48.69, 28.536)-(48.69, 27.536); L24 (43.69, 28.536)-(48.69, 28.536); L25 (48.19, 28.036)-(48.19, 27.536); L26 (48.19, 28.036)-(44.19, 28.036); L27 (48.69, 27.536)-(48.19, 27.536); L28 (37.19, 28.036)-(41.19, 28.036); L29 (41.69, 27.538)-(41.19, 27.538); L30 (41.69, 28.536)-(41.69, 27.538); L31 (41.19, 28.036)-(37.19, 28.036); L32 (37.19, 28.036)-(37.19, 27.538); L33 (36.75, 28.536)-(41.69, 28.536); L34 (37.19, 27.538)-(36.69, 27.538); L35 (36.69, 27.538)-(36.75, 28.536); L36 (41.19, 28.036)-(41.19, 27.538); L37 (3.25, 23.036)-(8.25, 23.036); L38 (8.25, 23.036)-(8.25, 20.036); L39 (8.25, 20.036)-(3.25, 20.036); L40 (3.25, 20.036)-(3.25, 23.036); L41 (7.75, 20.536)-(3.75, 20.536) reference; L42 (10.25, 23.036)-(15.161, 23.036); L43 (15.161, 23.036)-(15.161, 20.036); L44 (15.161, 20.036)-(10.25, 20.036); L45 (10.25, 20.036)-(10.25, 23.036); L46 (36.69, 23.036)-(41.69, 23.036); L47 (41.69, 23.036)-(41.69, 20.036); L48 (41.69, 20.036)-(36.69, 20.036); L49 (36.69, 20.036)-(36.69, 23.036); L50 (43.69, 23.036)-(48.61, 23.036); L51 (48.61, 23.036)-(48.61, 20.036); L52 (48.61, 20.036)-(43.69, 20.036); L53 (43.69, 20.036)-(43.69, 23.036); L54 (3.251, 5.5)-(8.25, 5.5); L55 (8.25, 5.5)-(8.25, 2.5); L56 (8.25, 2.5)-(3.251, 2.5); L57 (3.251, 2.5)-(3.251, 5.5); L58 (10.25, 5.5)-(15.161, 5.5); L59 (15.161, 5.5)-(15.161, 2.5); L60 (15.161, 2.5)-(10.25, 2.5); L61 (10.25, 2.5)-(10.25, 5.5); L62 (36.69, 5.5)-(41.69, 5.5); L63 (41.69, 5.5)-(41.69, 2.5); L64 (41.69, 2.5)-(36.69, 2.5)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; A1 r 2.5 centre (5.751, 10.436) between (8.251, 10.436) and (3.251, 10.436); A2 r 2 centre (5.751, 10.436) between (7.751, 10.436) and (3.751, 10.436); A3 r 2 centre (12.75, 10.436) between (14.75, 10.436) and (10.75, 10.436); A4 r 2.5 centre (12.75, 10.436) between (15.25, 10.436) and (10.25, 10.436); A5 r 2.014 centre (39.19, 10.436) between (41.19, 10.674) and (37.19, 10.674); A6 r 2.511 centre (39.19, 10.436) between (41.69, 10.674) and (36.69, 10.674); A7 r 2.014 centre (46.19, 10.436) between (48.19, 10.674) and (44.19, 10.674); A8 r 2.511 centre (46.19, 10.436) between (48.69, 10.674) and (43.69, 10.674); 1 further point
  constraints: 146 end point, 19 parallel, 16 point on circle, 15 perpendicular, 8 centre point, 8 horizontal, 7 collinear, 4 coincident, 2 point on line
  dimensions: "d2294" = 0.5 distance of L4.start L4.end; "d2297" = 1 distance of L4.end L5.end; "d2298" = 0.5 distance between parallel lines of L6 L2; "d2299" = 0 distance between parallel lines of L8 L4; "d2304" = 0.5 distance of L13.end L14.start; "d2306" = 1 distance of L14.start L14.end; "d2307" = 0 distance between parallel lines of L17 L15; "d2308" = 2 distance between parallel lines of L14 L7; "d2309" = 0 distance between parallel lines of L19 L6; "d2310" = 0.5 distance of L32.end L34.end; "d2311" = 0.5 distance of L29.start L29.end; "d2312" = 1 distance of L34.end L33.start; "d2313" = 0.5 distance between parallel lines of L33 L28; "d2314" = 0 distance between parallel lines of L29 L34; "d2315" = 0.5 distance of L21.end L20.start; "d2316" = 0.5 distance of L23.end L25.end; "d2317" = 1 distance of L20.start L20.end; "d2318" = 0 distance between parallel lines of L27 L22; "d2319" = 2 distance between parallel lines of L20 L30; "d2320" = 0 distance between parallel lines of L24 L33; "d2321" = 21.5 distance between parallel lines of L35 L18; "d2322" = 0 distance between parallel lines of L33 L19; "d2334" = 0.5 distance between parallel lines of L39 L41; "d2335" = 3 distance of L39.end L37.start; "d2336" = 3 distance of L56.end L54.start; "d2337" = 0 distance between parallel lines of L58 L54; "d2338" = 0 distance between parallel lines of L62 L58; "d2339" = 0 distance between parallel lines of L66 L62; "d2340" = 0 distance between parallel lines of L60 L56; "d2341" = 0 distance between parallel lines of L64 L60; "d2342" = 0 distance between parallel lines of L68 L64; "d2343" = 0.5 distance between parallel lines of L70 L56; "d2344" = 0 horizontal distance of L54.start L71.start; "d2346" = 2 distance of A2.centre L71.end; "d2348" = 2.5 distance of L71.start A1.centre; "d2349" = 0 vertical distance of L72.end L71.start; "d2350" = 2 distance of A3.centre L74.end; "d2352" = 2.5 distance of L74.start A4.centre; "d2353" = 0 vertical distance of L73.end L74.start; "d2354" = 2 horizontal distance of A5.centre L76.end; "d2356" = 2.5 horizontal distance of L76.start A6.centre; "d2357" = 0 vertical distance of L75.end L76.start; "d2362" = 0 distance between parallel lines of L74 L72; "d2363" = 0 distance from line of L77 A1.centre; "d2364" = 0 horizontal distance of L58.start L74.start; "d2366" = 0 vertical distance of A6.centre A4.centre; "d2367" = 2 horizontal distance of A7.centre L79.end; "d2368" = 2.5 horizontal distance of L79.start A8.centre; "d2369" = 0 vertical distance of L78.end L79.start; "d2370" = 0 distance between parallel lines of L79 L75; "d2371" = 0 distance from line of L69 L79.start; "d2374" = 0 distance between parallel lines of L55 L38; "d2375" = 0 distance between parallel lines of L59 L43; "d2376" = 0 distance between parallel lines of L69 L53; "d2377" = 0 distance between parallel lines of L67 L51; "d2378" = 0 distance between parallel lines of L45 L14; "d2379" = 0 distance between parallel lines of L61 L45; "d2380" = 0 distance from line of L65 L76.start; "d2381" = 0 distance between parallel lines of L53 L20; "d2382" = 0 distance between parallel lines of L47 L30; "d2383" = 0 distance between parallel lines of L63 L47; "d2384" = 0 distance from line of L63 L75.end; "d2385" = 0.5 distance of L75.start L75.end; "d2386" = 0 distance from line of L49 L34.end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
extrude "押し出し127" join sketch "スケッチ137" distance "d2388" = 0.5; taper "d2389" = 0 deg
sketch "スケッチ138"
  geometry: L1 (17, -13.4)-(17, -5.9) reference; L2 (4, -13.4)-(4, -5.9) reference; L3 (4, -5.9)-(8, -5.9) reference; L4 (8, -5.9)-(8, -13.4) reference; L5 (10.5, -13.4)-(10.5, -5.9) reference; L6 (24.5, -17.464)-(0.5, -17.464) reference; L7 (4, -6.4)-(3.5, -6.4); L8 (3.5, -6.4)-(3.5, -5.4); L9 (3.5, -5.4)-(8.5, -5.4); L10 (8.5, -5.4)-(8.5, -6.4); L11 (8.5, -6.4)-(8, -6.4); L12 (8, -6.4)-(8, -5.9); L13 (8, -5.9)-(4, -5.9); L14 (4, -5.9)-(4, -6.4); L15 (15, -6.4)-(14.5, -6.4); L16 (14.5, -6.4)-(14.5, -5.9); L17 (10.5, -5.9)-(14.5, -5.9); L18 (14.5, -5.9)-(10.5, -5.9); L19 (10, -5.4)-(15, -5.4); L20 (10.5, -5.9)-(10.5, -6.4); L21 (10.5, -6.4)-(10, -6.4); L22 (10, -6.4)-(10, -5.4); L23 (15, -5.4)-(15, -6.4); L24 (21.5, -6.4)-(21, -6.4); L25 (17, -6.4)-(16.5, -6.4); L26 (17, -5.9)-(17, -6.4); L27 (21, -5.9)-(17, -5.9); L28 (16.5, -6.4)-(16.5, -5.4); L29 (16.5, -5.4)-(21.5, -5.4); L30 (21, -6.4)-(21, -5.9); L31 (21.5, -5.4)-(21.5, -6.4); L32 (17, -5.9)-(21, -5.9); L33 (3.5, -10.882)-(8.5, -10.882); L34 (8.5, -10.882)-(8.5, -13.882); L35 (8.5, -13.882)-(3.5, -13.882); L36 (3.5, -13.882)-(3.5, -10.882); L37 (10, -10.961)-(15, -10.961); L38 (15, -10.961)-(15, -13.882); L39 (15, -13.882)-(10, -13.882); L40 (10, -13.882)-(10, -10.961); L41 (16.5, -10.961)-(21.5, -10.961); L42 (21.5, -10.961)-(21.5, -13.882); L43 (21.5, -13.882)-(16.5, -13.882); L44 (16.5, -13.882)-(16.5, -10.961); L45 (3.5, -28.5)-(8.5, -28.5); L46 (8.5, -28.5)-(8.5, -31.5); L47 (8.5, -31.5)-(3.5, -31.5); L48 (3.5, -31.5)-(3.5, -28.5); L49 (10, -28.5)-(15, -28.5); L50 (15, -28.5)-(15, -31.5); L51 (15, -31.5)-(10, -31.5); L52 (10, -31.5)-(10, -28.5); L53 (16.5, -28.537)-(21.5, -28.537); L54 (21.5, -28.537)-(21.5, -31.5); L55 (21.5, -31.5)-(16.5, -31.5); L56 (16.5, -31.5)-(16.5, -28.537); L57 (8, -31)-(4, -31) reference; L58 (3.5, -23.5)-(4, -23.5); L59 (8, -23.5)-(8.5, -23.5); L60 (14.5, -23.5)-(15, -23.5); L61 (10, -23.5)-(10.5, -23.5); L62 (21.5, -23.5)-(21, -23.5); L63 (17, -23.5)-(16.5, -23.5); A1 r 2.5 centre (6, -23.5) between (8.5, -23.5) and (3.5, -23.5); A2 r 2 centre (6, -23.5) between (8, -23.5) and (4, -23.5); A3 r 2 centre (12.5, -23.5) between (14.5, -23.5) and (10.5, -23.5); A4 r 2.5 centre (12.5, -23.5) between (15, -23.5) and (10, -23.5); A5 r 2 centre (19, -23.5) between (21, -23.5) and (17, -23.5); A6 r 2.5 centre (19, -23.5) between (21.5, -23.5) and (16.5, -23.5); 1 further point
  constraints: 112 end point, 20 parallel, 12 point on circle, 11 perpendicular, 6 centre point, 6 horizontal, 5 collinear, 3 coincident, 2 point on line
  dimensions: "d2390" = 0.5 distance of L7.start L7.end; "d2392" = 0.5 distance of L10.end L11.end; "d2393" = 1 distance of L7.end L8.end; "d2394" = 0.5 distance between parallel lines of L9 L3; "d2395" = 0.5 distance of L20.end L21.end; "d2396" = 0.5 distance of L15.start L15.end; "d2397" = 1 distance of L21.end L19.start; "d2398" = 0.5 distance between parallel lines of L19 L17; "d2399" = 0.5 distance of L25.start L25.end; "d2400" = 0.5 distance of L24.start L24.end; "d2401" = 1 distance of L25.end L28.end; "d2402" = 0.5 distance between parallel lines of L29 L32; "d2403" = 0 distance between parallel lines of L21 L11; "d2404" = 0 distance from line of L10.end L7; "d2405" = 0 distance between parallel lines of L15 L21; "d2406" = 0 distance between parallel lines of L25 L15; "d2407" = 0 distance between parallel lines of L24 L25; "d2408" = 0 distance between parallel lines of L5 L20; "d2409" = 0 distance between parallel lines of L26 L1; "d2410" = 5 distance of L19.start L19.end; "d2411" = 5 distance of L28.end L29.end; "d2412" = 3 distance of L35.end L33.start; "d2413" = 0 distance between parallel lines of L36 L8; "d2414" = 0 distance between parallel lines of L48 L36; "d2415" = 5 distance of L34.end L35.end; "d2416" = 0 distance between parallel lines of L46 L34; "d2417" = 5 distance of L38.end L39.end; "d2418" = 1.5 distance between parallel lines of L40 L34; "d2419" = 0 distance between parallel lines of L52 L40; "d2420" = 0 distance between parallel lines of L50 L38; "d2421" = 3 distance of L47.end L45.start; "d2422" = 0.5 distance between parallel lines of L47 L57; "d2423" = 0 distance between parallel lines of L51 L47; "d2424" = 0 distance between parallel lines of L55 L51; "d2425" = 0 distance between parallel lines of L49 L45; "d2426" = 0 vertical distance of L59.start L58.end; "d2427" = 0 distance from line of L48 L58.start; "d2428" = 0 distance from line of L46 L59.end; "d2429" = 0.5 distance of L58.start L58.end; "d2430" = 5 distance between parallel lines of L45 L58; "d2431" = 0 vertical distance of L60.start L61.end; "d2432" = 0.5 distance of L61.start L61.end; "d2433" = 0 horizontal distance of L49.start L61.start; "d2434" = 0 vertical distance of A1.centre A4.centre; "d2435" = 0 vertical distance of L59.end L61.start; "d2436" = 0 distance from line of L50 L60.end; "d2437" = 0 distance from line of A1.centre L58; "d2438" = 0 vertical distance of L62.start L63.end; "d2439" = 0.5 distance of L63.start L63.end; "d2440" = 0 horizontal distance of L53.start L63.end; "d2441" = 0 distance between parallel lines of L56 L44; "d2442" = 0 distance between parallel lines of L44 L28; "d2443" = 0 vertical distance of A4.centre A6.centre; "d2444" = 0 distance from line of L54 L62.start; "d2445" = 0 distance between parallel lines of L54 L42; "d2446" = 0 distance between parallel lines of L42 L31; "d2447" = 0 vertical distance of L60.end L63.end; "d2448" = 0 vertical distance of L63.start L60.end; "d2450" = 0 vertical distance of L61.start L61.end
extrude "押し出し128" join sketch "スケッチ138" distance "d2451" = 0.5; taper "d2452" = 0 deg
